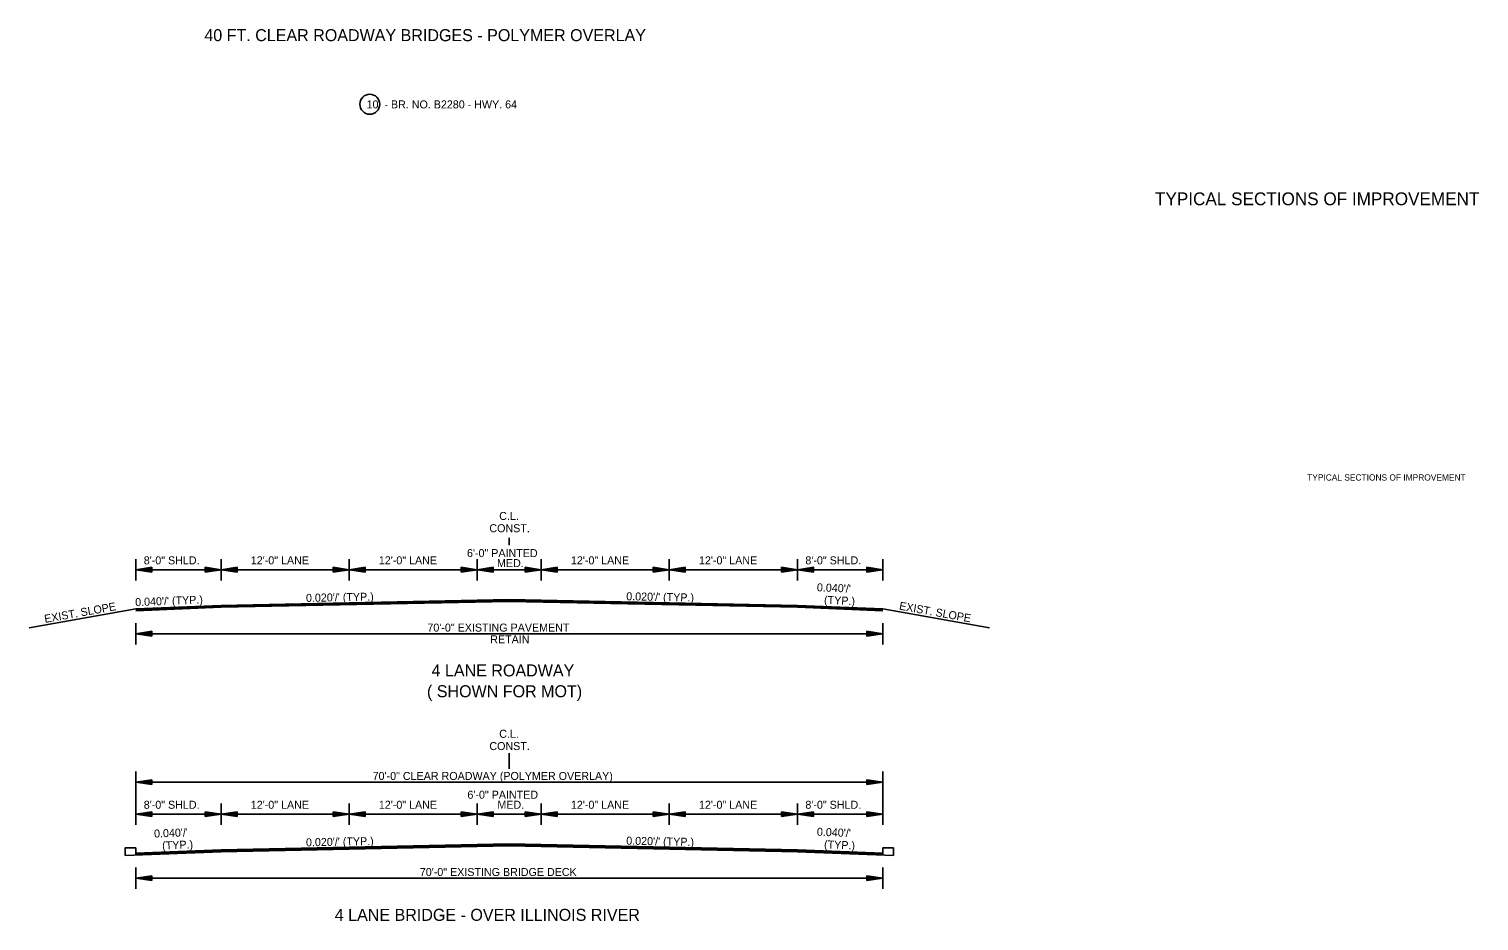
# Model space of a CAD drawing. Extents: x 550980 to 1930787, y -1972975 to 596640.
# Drawn here: x 551187 to 552546, y -1949853 to -1949017 of the extents above; entities that cross this region are included whole.
import ezdxf

# ---------------------------------------------------------------- set-up
doc = ezdxf.new("R2010")
doc.units = 0
for name, color, linetype in [('R_Border', 7, 'Continuous'), ('R_Draft', 7, 'Continuous'), ('S_AREA_CALC', 7, 'Continuous')]:
    doc.layers.add(name, color=color, linetype=linetype)

# ---------------------------------------------------------------- blocks, each defined once
blk = doc.blocks.new('ARROW')
at = {"layer": 'R_Draft'}
for p, q in [((-2, 0.3), (0, 0)), ((-2, 0.3), (-2, -0.3)), ((-2, 0.25), (-0.334, 0)), ((-2, 0.199), (-0.678, 0)), ((-2, 0.149), (-1.011, 0)), ((-2, 0.097), (-1.35, 0)), ((-2, 0.047), (-1.684, 0)), ((-2, -0.3), (0, 0)), ((-2, -0.098), (-1.35, 0)), ((-2, -0.199), (-0.678, 0)), ((-2, -0.25), (-0.334, 0)), ((-2, -0.149), (-1.011, 0)), ((-2, -0.047), (-1.684, 0))]:
    blk.add_line(p, q, dxfattribs=at)

msp = doc.modelspace()

# ---------------------------------------------------------------- linework, layer by layer
at = {"layer": 'R_Border'}
for p, q in [((551637.2, -1949493.8), (551637.2, -1949500.7)), ((551287.2, -1949513.6), (551287.2, -1949533.6)), ((551367.2, -1949513.6), (551367.2, -1949533.6)), ((551487.2, -1949513.6), (551487.2, -1949533.6)), ((551607.2, -1949513.6), (551607.2, -1949533.6)), ((551667.2, -1949513.6), (551667.2, -1949533.6)), ((551787.2, -1949513.6), (551787.2, -1949533.6)), ((551907.2, -1949513.6), (551907.2, -1949533.6)), ((551987.2, -1949513.6), (551987.2, -1949533.6)), ((551287.2, -1949523.6), (551987.2, -1949523.6)), ((551287.2, -1949560.2), (551187.2, -1949578.2)), ((551987.2, -1949560.2), (552087.2, -1949578.2)), ((551287.2, -1949573.6), (551287.2, -1949593.6)), ((551987.2, -1949573.6), (551987.2, -1949593.6)), ((551287.2, -1949583.6), (551987.2, -1949583.6)), ((551637.2, -1949695.6), (551637.2, -1949710.1)), ((551287.2, -1949712.6), (551287.2, -1949762.6)), ((551287.2, -1949722.6), (551987.2, -1949722.6)), ((551987.2, -1949712.6), (551987.2, -1949762.6)), ((551367.2, -1949742.6), (551367.2, -1949762.6)), ((551487.2, -1949742.6), (551487.2, -1949762.6)), ((551607.2, -1949742.6), (551607.2, -1949762.6)), ((551667.2, -1949742.6), (551667.2, -1949762.6)), ((551787.2, -1949742.6), (551787.2, -1949762.6)), ((551907.2, -1949742.6), (551907.2, -1949762.6)), ((551287.2, -1949752.6), (551987.2, -1949752.6)), ((551287.2, -1949802.6), (551287.2, -1949822.6)), ((551987.2, -1949802.6), (551987.2, -1949822.6)), ((551287.2, -1949812.6), (551987.2, -1949812.6))]:
    msp.add_line(p, q, dxfattribs=at)
for points in [[(551287.2, -1949560.2), (551367.2, -1949557), (551637.2, -1949551.6), (551907.2, -1949557), (551987.2, -1949560.2)], [(551287.2, -1949560.5), (551367.2, -1949557.3), (551637.2, -1949551.9), (551907.2, -1949557.3), (551987.2, -1949560.5)], [(551287.2, -1949560.8), (551367.2, -1949557.6), (551637.2, -1949552.2), (551907.2, -1949557.6), (551987.2, -1949560.8)], [(551287.2, -1949561.1), (551367.2, -1949557.9), (551637.2, -1949552.5), (551907.2, -1949557.9), (551987.2, -1949561.1)], [(551287.2, -1949561.4), (551367.2, -1949558.2), (551637.2, -1949552.8), (551907.2, -1949558.2), (551987.2, -1949561.4)], [(551287.2, -1949561.7), (551367.2, -1949558.5), (551637.2, -1949553.1), (551907.2, -1949558.5), (551987.2, -1949561.7)], [(551287.2, -1949562), (551367.2, -1949558.8), (551637.2, -1949553.4), (551907.2, -1949558.8), (551987.2, -1949562)], [(551277.2, -1949791.4), (551367.2, -1949787.8), (551637.2, -1949782.4), (551907.2, -1949787.8), (551997.2, -1949791.4)], [(551287.2, -1949790.7), (551287.2, -1949784.2), (551277.2, -1949784.2), (551277.2, -1949791.4)], [(551287.2, -1949789.2), (551367.2, -1949786), (551637.2, -1949780.6), (551907.2, -1949786), (551987.2, -1949789.2)], [(551287.2, -1949789.5), (551367.2, -1949786.3), (551637.2, -1949780.9), (551907.2, -1949786.3), (551987.2, -1949789.5)], [(551287.2, -1949789.8), (551367.2, -1949786.6), (551637.2, -1949781.2), (551907.2, -1949786.6), (551987.2, -1949789.8)], [(551287.2, -1949790.1), (551367.2, -1949786.9), (551637.2, -1949781.5), (551907.2, -1949786.9), (551987.2, -1949790.1)], [(551287.2, -1949790.4), (551367.2, -1949787.2), (551637.2, -1949781.8), (551907.2, -1949787.2), (551987.2, -1949790.4)], [(551287.2, -1949790.7), (551367.2, -1949787.5), (551637.2, -1949782.1), (551907.2, -1949787.5), (551987.2, -1949790.7)], [(551987.2, -1949791.4), (551987.2, -1949784.2), (551997.2, -1949784.2), (551997.2, -1949791.4)]]:
    msp.add_lwpolyline(points, dxfattribs=at)
msp.add_circle((551506.5, -1949087.5), 9.34, dxfattribs=at)

# ---------------------------------------------------------------- block references
at = {"layer": 'R_Border', "xscale": 7.5, "yscale": 7.5, "rotation": 180}
for p in [(551287.2, -1949523.6), (551367.2, -1949523.6), (551487.2, -1949523.6), (551607.2, -1949523.6), (551667.2, -1949523.6), (551787.2, -1949523.6), (551907.2, -1949523.6), (551287.2, -1949583.6), (551287.2, -1949722.6), (551287.2, -1949752.6), (551367.2, -1949752.6), (551487.2, -1949752.6), (551607.2, -1949752.6), (551667.2, -1949752.6), (551787.2, -1949752.6), (551907.2, -1949752.6), (551287.2, -1949812.6)]:
    msp.add_blockref('ARROW', p, dxfattribs=at)
at = {"layer": 'R_Border', "xscale": 7.5, "yscale": 7.5}
for p in [(551367.2, -1949523.6), (551487.2, -1949523.6), (551607.2, -1949523.6), (551667.2, -1949523.6), (551787.2, -1949523.6), (551907.2, -1949523.6), (551987.2, -1949523.6), (551987.2, -1949583.6), (551987.2, -1949722.6), (551367.2, -1949752.6), (551487.2, -1949752.6), (551607.2, -1949752.6), (551667.2, -1949752.6), (551787.2, -1949752.6), (551907.2, -1949752.6), (551987.2, -1949752.6), (551987.2, -1949812.6)]:
    msp.add_blockref('ARROW', p, dxfattribs=at)

# ---------------------------------------------------------------- texts
at = {"layer": 'R_Border'}
for s, height, rotation, p in [('TYPICAL SECTIONS OF IMPROVEMENT', 12, 360, (552242.3, -1949182.1)), ("0.040'/' (TYP.)", 7.5, 2.2916, (551286.8, -1949557.8)), ("0.020'/' (TYP.)", 7.5, 1.1458, (551446.8, -1949553.8)), ("0.020'/' (TYP.)", 7.5, 358.8542, (551746.8, -1949552.2)), ("0.040'/'", 7.5, 357.7084, (551925.4, -1949543.8)), ('(TYP.)', 7.5, 357.7084, (551932.1, -1949555.6)), ('EXIST. SLOPE', 7.5, 10.204, (551202.2, -1949573.5)), ('EXIST. SLOPE', 7.5, 349.796, (552002.2, -1949560.9)), ("0.040'/'", 7.5, 357.7084, (551925.4, -1949772.8)), ("0.040'/'", 7.5, 2.2916, (551304.5, -1949774.6)), ('(TYP.)', 7.5, 2.2916, (551312.1, -1949785.8)), ("0.020'/' (TYP.)", 7.5, 1.1458, (551446.8, -1949782.8)), ("0.020'/' (TYP.)", 7.5, 358.8542, (551746.8, -1949781.2)), ('(TYP.)', 7.5, 357.7084, (551932.1, -1949784.6))]:
    msp.add_text(s, height=height, rotation=rotation, dxfattribs=at).set_placement(p)
for s, height, p in [('C.L.', 7.5, (551627.8, -1949477)), ('CONST.', 7.5, (551618.6, -1949488.5)), ('6\'-0" PAINTED', 7.5, (551597.6, -1949511.8)), ('8\'-0" SHLD.', 7.5, (551294.7, -1949518.6)), ('12\'-0" LANE', 7.5, (551395, -1949518.6)), ('12\'-0" LANE', 7.5, (551515, -1949518.6)), ('MED.', 7.5, (551625.7, -1949521.2)), ('12\'-0" LANE', 7.5, (551695, -1949518.6)), ('12\'-0" LANE', 7.5, (551815, -1949518.6)), ('8\'-0" SHLD.', 7.5, (551914.7, -1949518.6)), ('70\'-0" EXISTING PAVEMENT', 7.5, (551560.5, -1949581.6)), ('RETAIN', 7.5, (551619.4, -1949592.6)), ('4 LANE ROADWAY', 11.25, (551564.4, -1949623.6)), ('( SHOWN FOR MOT)', 11.25, (551560.1, -1949643.1)), ('C.L.', 7.5, (551627.8, -1949681.1)), ('CONST.', 7.5, (551618.6, -1949692.6)), ('70\'-0" CLEAR ROADWAY (POLYMER OVERLAY)', 7.5, (551509.2, -1949720.6)), ('6\'-0" PAINTED', 7.5, (551598, -1949738.2)), ('8\'-0" SHLD.', 7.5, (551294.7, -1949747.6)), ('12\'-0" LANE', 7.5, (551395, -1949747.6)), ('12\'-0" LANE', 7.5, (551515, -1949747.6)), ('MED.', 7.5, (551626.1, -1949747.6)), ('12\'-0" LANE', 7.5, (551695, -1949747.6)), ('12\'-0" LANE', 7.5, (551815, -1949747.6)), ('8\'-0" SHLD.', 7.5, (551914.7, -1949747.6)), ('70\'-0" EXISTING BRIDGE DECK', 7.5, (551553.4, -1949810.6)), ('4 LANE BRIDGE - OVER ILLINOIS RIVER', 11.25, (551473.7, -1949852.6))]:
    msp.add_text(s, height=height, dxfattribs=at).set_placement(p)
at = {"layer": 'R_Draft'}
for s, height, p in [('40 FT. CLEAR ROADWAY BRIDGES - POLYMER OVERLAY', 11.25, (551351.5, -1949028.4)), ('10  - BR. NO. B2280 - HWY. 64', 7.5, (551503.5, -1949091.4))]:
    msp.add_text(s, height=height, dxfattribs=at).set_placement(p)
at = {"layer": 'S_AREA_CALC'}
msp.add_text('TYPICAL SECTIONS OF IMPROVEMENT', height=5.862, rotation=360, dxfattribs=at).set_placement((552384.9, -1949440.1))

doc.saveas('drawing.dxf')
